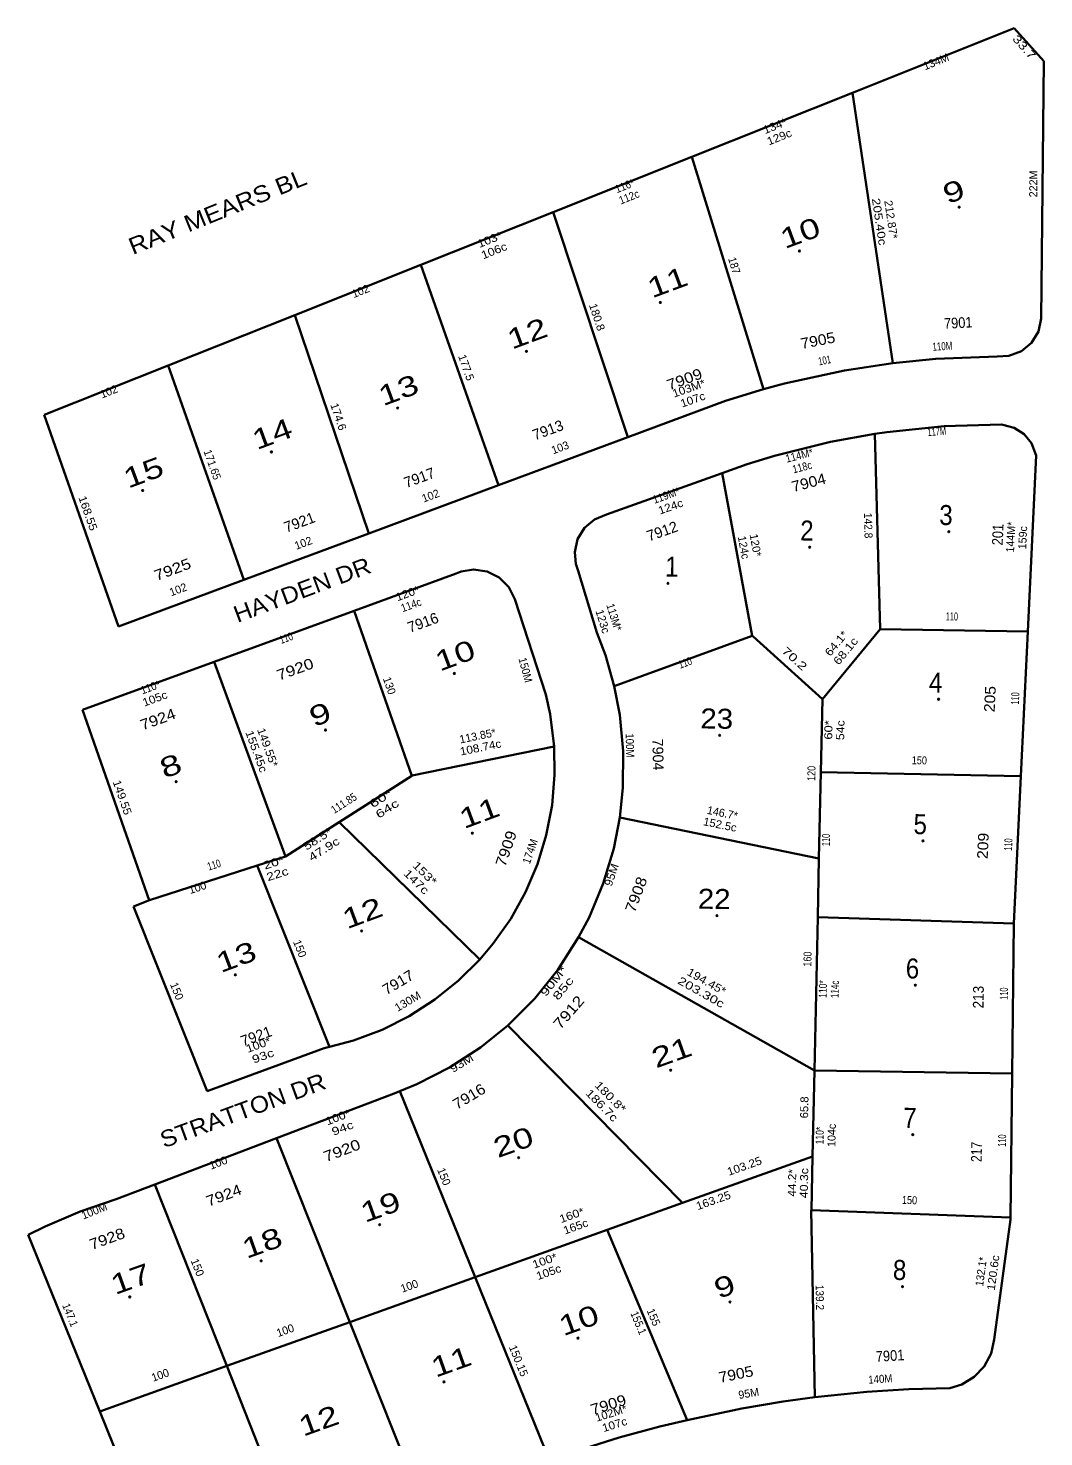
# Model space of a CAD drawing. Extents: x 2546959 to 2550387, y 581906 to 585027.
# Drawn here: x 2547465 to 2548226, y 583970 to 585027 of the extents above; entities that cross this region are included whole.
import ezdxf
from ezdxf.enums import TextEntityAlignment as Align

# ---------------------------------------------------------------- set-up
doc = ezdxf.new("R2010")
doc.units = 0
doc.header["$LTSCALE"] = 2.4
doc.header["$PDMODE"] = 32
doc.header["$PDSIZE"] = 1.2
for name, color, linetype in [('20', 7, 'Continuous'), ('38', 7, 'Continuous'), ('39', 7, 'Continuous'), ('41', 7, 'Continuous'), ('42', 7, 'Continuous')]:
    doc.layers.add(name, color=color, linetype=linetype)
doc.layers.add('40', color=7, linetype='Continuous', lineweight=35)

msp = doc.modelspace()

# ---------------------------------------------------------------- linework, layer by layer
at = {"layer": '40'}
for p, q in [((2548204.014, 585026.501), (2548082.739, 584978.146)), ((2548226.245, 585001.697), (2548204.014, 585026.501)), ((2548224.277, 584808.852), (2548226.245, 585001.697)), ((2548082.739, 584978.146), (2547962.303, 584930.126)), ((2548112.924, 584775.333), (2548082.739, 584978.146)), ((2547962.303, 584930.126), (2547858.204, 584888.62)), ((2548016.151, 584755.782), (2547962.303, 584930.126)), ((2547858.204, 584888.62), (2547759.114, 584849.112)), ((2547914.388, 584719.889), (2547858.204, 584888.62)), ((2547759.114, 584849.112), (2547664.568, 584811.416)), ((2547817.297, 584683.807), (2547759.114, 584849.112)), ((2547664.568, 584811.416), (2547569.517, 584773.517)), ((2547720.206, 584647.727), (2547664.568, 584811.416)), ((2547569.517, 584773.517), (2547476.689, 584736.505)), ((2547626.39, 584612.862), (2547569.517, 584773.517)), ((2547987.542, 584747.075), (2548016.151, 584755.782)), ((2547914.388, 584719.889), (2547987.542, 584747.075)), ((2547476.689, 584736.505), (2547532.448, 584577.95)), ((2547817.297, 584683.807), (2547914.388, 584719.889)), ((2548103.512, 584576.042), (2548099.538, 584722.294)), ((2548003.755, 584699.71), (2547984.922, 584692.969)), ((2548214.27, 584574.238), (2548220.537, 584706.084)), ((2547984.922, 584692.969), (2547898.412, 584662.004)), ((2548007.585, 584570.978), (2547984.922, 584692.969)), ((2547720.206, 584647.727), (2547817.297, 584683.807)), ((2547626.39, 584612.862), (2547720.206, 584647.727)), ((2547532.448, 584577.95), (2547626.39, 584612.862)), ((2547709.072, 584589.763), (2547785.46, 584617.652)), ((2547829.533, 584598.297), (2547852.84, 584526.961)), ((2547752.252, 584465.989), (2547709.072, 584589.763)), ((2548007.585, 584570.978), (2547904.091, 584533.141)), ((2548008.322, 584570.311), (2548007.585, 584570.978)), ((2548060.181, 584523.422), (2548008.322, 584570.311)), ((2548060.181, 584523.422), (2548103.512, 584576.042)), ((2548103.512, 584576.042), (2548214.27, 584574.238)), ((2548209.112, 584465.708), (2548214.27, 584574.238)), ((2547505.384, 584515.396), (2547604.222, 584551.482)), ((2547505.384, 584515.396), (2547555.274, 584372.68)), ((2547697.97, 584431.3), (2547752.252, 584465.989)), ((2548209.112, 584465.708), (2548059.011, 584468.839)), ((2548203.861, 584355.253), (2548209.112, 584465.708)), ((2548057.619, 584403.911), (2547908.224, 584434.685)), ((2547657.54, 584405.464), (2547697.97, 584431.3)), ((2547697.97, 584431.3), (2547803.347, 584328.288)), ((2547636.483, 584398.714), (2547657.54, 584405.464)), ((2547636.483, 584398.714), (2547690.507, 584262.679)), ((2547555.553, 584372.77), (2547543.687, 584368.085)), ((2547543.687, 584368.085), (2547598.762, 584229.478)), ((2548203.861, 584355.253), (2548202.493, 584242.777)), ((2548054.214, 584245.13), (2547877.415, 584344.957)), ((2547955.225, 584145.719), (2547824.237, 584278.814)), ((2547686.611, 584261.811), (2547598.762, 584229.478)), ((2547690.507, 584262.679), (2547686.611, 584261.811)), ((2548052.831, 584180.633), (2548054.214, 584245.13)), ((2548202.493, 584242.777), (2548201.181, 584134.88)), ((2547739.134, 584227.906), (2547650.734, 584194.276)), ((2547743.36, 584229.523), (2547739.134, 584227.906)), ((2547799.804, 584090.124), (2547743.36, 584229.523)), ((2547650.734, 584194.276), (2547559.711, 584159.647)), ((2547705.757, 584056.483), (2547650.734, 584194.276)), ((2547955.225, 584145.719), (2548052.831, 584180.633)), ((2548051.967, 584140.339), (2548052.831, 584180.633)), ((2547559.711, 584159.647), (2547530.552, 584148.553)), ((2547613.638, 584023.531), (2547559.711, 584159.647)), ((2548054.645, 584000.017), (2548051.866, 584140.342)), ((2548051.967, 584140.339), (2548051.866, 584140.342)), ((2548201.181, 584134.88), (2548051.967, 584140.339)), ((2548201.161, 584133.322), (2548189.038, 584043.393)), ((2548201.181, 584134.88), (2548201.161, 584133.322)), ((2547518.285, 583989.423), (2547464.644, 584121.761)), ((2547668.847, 583883.672), (2547613.66, 584023.54))]:
    msp.add_line(p, q, dxfattribs=at)
for points in [[(2548191.184, 584780.398), (2548200.115, 584780.809), (2548209.399, 584784.32), (2548217.032, 584790.665), (2548222.178, 584799.151), (2548224.277, 584808.852)], [(2548112.924, 584775.333), (2548145.178, 584778.626), (2548191.184, 584780.398)], [(2548016.151, 584755.782), (2548031.713, 584760.06), (2548076.691, 584769.891), (2548112.924, 584775.333)], [(2548194.544, 584729.359), (2548151.485, 584728.054), (2548108.625, 584723.707), (2548099.538, 584722.294)], [(2548220.537, 584706.084), (2548217.082, 584715.276), (2548211.48, 584722.12), (2548204.06, 584726.936), (2548195.544, 584729.191), (2548194.544, 584729.359)], [(2548099.538, 584722.294), (2548066.18, 584716.339), (2548024.363, 584705.988), (2548003.755, 584699.71)], [(2547898.412, 584662.004), (2547889.229, 584658.263), (2547881.71, 584651.797), (2547876.634, 584643.278), (2547874.528, 584633.588), (2547875.333, 584624.802), (2547877.097, 584619.566), (2547891.035, 584573.532)], [(2547785.46, 584617.652), (2547789.21, 584619.054), (2547798.645, 584620.715), (2547808.722, 584619.231), (2547817.816, 584614.642), (2547824.998, 584607.418), (2547829.533, 584598.297)], [(2547657.54, 584405.464), (2547604.222, 584551.482), (2547709.072, 584589.763)], [(2547891.035, 584573.532), (2547897.495, 584556.359), (2547904.091, 584533.141)], [(2547852.84, 584526.961), (2547856.068, 584512.098), (2547859.021, 584487.888)], [(2547904.091, 584533.141), (2547908.238, 584511.815), (2547910.874, 584484.426), (2547910.612, 584456.912), (2547908.224, 584434.685)], [(2548203.861, 584355.253), (2548056.679, 584360.068), (2548057.619, 584403.911), (2548059.011, 584468.839), (2548060.181, 584523.422)], [(2547752.252, 584465.989), (2547752.479, 584466.134), (2547859.021, 584487.888)], [(2547859.021, 584487.888), (2547859.399, 584466.668), (2547857.459, 584443.942), (2547853.138, 584421.547), (2547846.481, 584399.732), (2547837.564, 584378.739), (2547826.485, 584358.802), (2547813.367, 584340.144), (2547803.347, 584328.288)], [(2547908.224, 584434.685), (2547903.752, 584411.608), (2547895.859, 584385.249), (2547885.232, 584359.868), (2547877.415, 584344.957)], [(2547555.274, 584372.68), (2547555.553, 584372.77), (2547636.483, 584398.714)], [(2548202.493, 584242.777), (2548054.214, 584245.13), (2548056.679, 584360.068)], [(2547877.415, 584344.957), (2547861.784, 584320.502), (2547844.527, 584299.07), (2547824.237, 584278.814)], [(2547803.347, 584328.288), (2547787.382, 584312.442), (2547769.599, 584298.159), (2547750.411, 584285.83), (2547730.03, 584275.59), (2547708.684, 584267.554), (2547690.507, 584262.679)], [(2547824.237, 584278.814), (2547803.746, 584262.235), (2547780.676, 584247.241), (2547756.154, 584234.761), (2547743.36, 584229.523)], [(2547530.552, 584148.553), (2547503.636, 584139.218), (2547477.436, 584128.032), (2547464.644, 584121.761)], [(2547958.685, 583982.997), (2547898.743, 584125.514), (2547955.225, 584145.719)], [(2547855.466, 583952.653), (2547799.804, 584090.124), (2547898.743, 584125.514)], [(2547761.113, 583917.857), (2547705.757, 584056.483), (2547799.804, 584090.124)], [(2547613.638, 584023.531), (2547613.66, 584023.54), (2547705.757, 584056.483)], [(2548155.677, 584006.992), (2548164.796, 584009.704), (2548174.102, 584015.309), (2548181.577, 584023.194), (2548186.68, 584032.787), (2548189.038, 584043.393)], [(2547575.211, 583848.979), (2547518.285, 583989.423), (2547613.638, 584023.531)], [(2547958.685, 583982.997), (2547999.751, 583991.67), (2548030.843, 583996.867), (2548054.645, 584000.017)], [(2548054.645, 584000.017), (2548093.467, 584004.073), (2548124.926, 584006.073), (2548155.677, 584006.992)], [(2547855.466, 583952.653), (2547877.689, 583960.409), (2547907.788, 583969.778), (2547938.188, 583978.118), (2547958.685, 583982.997)]]:
    msp.add_lwpolyline(points, dxfattribs=at)
at = {"layer": '41'}
for p in [(2548162.752, 584892.32), (2548043.004, 584859.485), (2547938.708, 584820.856), (2547838.274, 584784.159), (2547741.704, 584741.667), (2547647.064, 584708.833), (2547550.494, 584679.862), (2548155.025, 584648.96), (2548050.729, 584637.372), (2547944.501, 584610.332), (2547784.194, 584542.731), (2548147.299, 584523.418), (2547687.623, 584500.24), (2547983.129, 584496.378), (2547575.601, 584461.611), (2547797.714, 584422.983), (2548135.71, 584417.19), (2547981.197, 584361.178), (2547714.663, 584349.588), (2547620.023, 584316.754), (2548129.916, 584309.03), (2547946.432, 584245.293), (2548127.984, 584197.008), (2547832.478, 584179.624), (2547728.182, 584129.406), (2547639.337, 584102.366), (2548120.258, 584083.054), (2547540.835, 584075.326), (2547990.854, 584071.464), (2547876.9, 584044.424), (2547776.467, 584011.59)]:
    msp.add_point(p, dxfattribs=at)

# ---------------------------------------------------------------- texts
at = {"layer": '20'}
for s, rotation, width, p in [('RAY MEARS BL', 22.079, 1.15, (2547608.953, 584883.111)), ('HAYDEN DR', 20.548, 1.1, (2547672.257, 584599.551)), ('STRATTON DR', 20.187, 1.1, (2547627.783, 584209.234))]:
    msp.add_text(s, height=12.5, rotation=rotation, dxfattribs=dict(at, width=width)).set_placement(p, align=Align.CENTER)
at = {"layer": '38'}
for s, rotation, width, p in [('9', 20.386, 1.4, (2548161.296, 584897.085)), ('10', 20.386, 1.35, (2548046.161, 584866.066)), ('11', 20.386, 1.35, (2547946.545, 584829.075)), ('12', 20.386, 1.35, (2547841.47, 584790.653)), ('13', 20.386, 1.35, (2547744.885, 584748.2)), ('14', 20.386, 1.35, (2547650.22, 584715.347)), ('15', 20.386, 1.35, (2547553.688, 584686.44)), ('3', 359.091, 0.9, (2548152.769, 584653.988)), ('2', 359.091, 0.9, (2548048.45, 584642.361)), ('1', 359.091, 0.9, (2547947.172, 584615.296)), ('10', 20.386, 1.35, (2547787.39, 584549.269)), ('4', 359.091, 0.9, (2548145.035, 584528.443)), ('9', 20.386, 1.4, (2547686.155, 584505.088)), ('23', 359.091, 1.1, (2547980.878, 584501.35)), ('8', 20.386, 1.4, (2547574.103, 584466.474)), ('11', 20.386, 1.35, (2547805.532, 584431.211)), ('5', 359.091, 0.9, (2548133.462, 584422.204)), ('22', 359.091, 1.1, (2547978.957, 584366.204)), ('12', 20.386, 1.35, (2547717.844, 584356.097)), ('13', 20.386, 1.35, (2547623.179, 584323.244)), ('6', 359.091, 0.9, (2548127.648, 584314.045)), ('21', 19.682, 1.35, (2547949.625, 584251.651)), ('7', 359.091, 0.9, (2548125.728, 584202.046)), ('20', 19.682, 1.35, (2547830.982, 584184.38)), ('19', 19.682, 1.35, (2547731.334, 584135.811)), ('18', 19.682, 1.35, (2547642.536, 584108.825)), ('17', 19.682, 1.35, (2547544.031, 584081.731)), ('8', 359.091, 0.9, (2548117.994, 584088.02)), ('9', 19.682, 1.35, (2547989.379, 584076.222)), ('10', 19.682, 1.35, (2547880.079, 584050.799)), ('11', 19.682, 1.35, (2547784.324, 584019.723)), ('12', 19.682, 1.35, (2547684.988, 583975.493))]:
    msp.add_text(s, height=15, rotation=rotation, dxfattribs=dict(at, width=width)).set_placement(p, align=Align.CENTER)
at = {"layer": '39'}
for s, rotation, width, p in [('7901', 3.218, 0.9, (2548162.286, 584801.623)), ('7905', 11.318, 1.1, (2548057.568, 584788.457)), ('7909', 20.386, 1.15, (2547958.146, 584759.551)), ('7904', 14.917, 1.1, (2548050.963, 584681.966)), ('201', 87.279, 0.9, (2548195.683, 584646.653)), ('7925', 20.387, 1.2, (2547574.257, 584616.937)), ('7920', 20.057, 1.2, (2547666.159, 584542.14)), ('205', 87.279, 1.1, (2548189.811, 584523.318)), ('7924', 20.057, 1.15, (2547563.281, 584504.594)), ('7909', 71.017, 1.15, (2547826.789, 584410.146)), ('209', 87.279, 1.1, (2548184.585, 584413.24)), ('7908', 69.293, 1.15, (2547924.274, 584375.587)), ('7917', 30.71, 1.05, (2547744.054, 584307.711)), ('213', 89.303, 0.95, (2548181.137, 584300.02)), ('7912', 49.143, 1.2, (2547873.001, 584286.096)), ('7916', 31.003, 1.1, (2547797.322, 584222.189)), ('7920', 20.829, 1.2, (2547701.299, 584181.35)), ('217', 89.303, 0.85, (2548179.751, 584183.968)), ('7924', 20.829, 1.15, (2547612.767, 584147.75)), ('7928', 20.125, 1.15, (2547525.209, 584115.163)), ('7901', 3.638, 0.9, (2548111.197, 584027.229)), ('7905', 11.44, 1.1, (2547996.197, 584013.43)), ('7909', 17.29, 1.15, (2547900.881, 583990.701))]:
    msp.add_text(s, height=8, rotation=rotation, dxfattribs=dict(at, width=width)).set_placement(p, align=Align.CENTER)
for s, rotation, p in [('7913', 20.386, (2547855.743, 584721.49)), ('7917', 20.386, (2547759.371, 584685.756)), ('7921', 20.386, (2547669.442, 584652.309)), ('7912', 19.694, (2547941.455, 584645.626)), ('7916', 20.057, (2547762.043, 584577.16)), ('7904', 271.467, (2547932.962, 584481.833)), ('7921', 20.206, (2547636.99, 584267.022))]:
    msp.add_text(s, height=8, rotation=rotation, dxfattribs=at).set_placement(p, align=Align.CENTER)
at = {"layer": '42'}
for s, rotation, width, p in [('33.7', 311.868, 1.35, (2548209.268, 585010.333)), ('134*', 21.738, 1.1, (2548025.661, 584950.415)), ('129c', 21.738, 1.1, (2548028.967, 584942.094)), ('116*', 21.738, 0.9, (2547913.044, 584905.475)), ('112c', 21.738, 0.9, (2547916.351, 584897.154)), ('205.40c', 278.465, 1.25, (2548099.927, 584880.975)), ('212.87*', 278.465, 1.05, (2548108.724, 584882.629)), ('103*', 21.738, 1.15, (2547811.796, 584865.189)), ('106c', 21.738, 1.15, (2547815.103, 584856.868)), ('187', 287.164, 0.95, (2547991.272, 584847.702)), ('180.8', 288.417, 1.05, (2547888.394, 584808.962)), ('110M', 3.703, 0.75, (2548150.353, 584785.07)), ('101', 11.318, 0.65, (2548062.418, 584774.558)), ('103M*', 19.429, 1.1, (2547961.003, 584753.71)), ('107c', 19.429, 1.1, (2547963.989, 584745.178)), ('174.6', 288.773, 1.05, (2547694.493, 584734.26)), ('117M', 4.253, 0.7, (2548146.198, 584721.176)), ('171.65', 289.494, 0.95, (2547599.95, 584698.275)), ('114M*', 14.352, 0.9, (2548043.53, 584703.277)), ('118c', 14.352, 0.85, (2548045.77, 584694.53)), ('168.55', 289.375, 1.1, (2547506.685, 584661.879)), ('119M*', 19.694, 0.9, (2547944.033, 584673.383)), ('124c', 19.694, 1.1, (2547947.376, 584664.978)), ('142.8', 271.556, 0.95, (2548091.607, 584653.488)), ('120*', 280.524, 1.05, (2548007.165, 584638.363)), ('120*', 20.057, 1.1, (2547750.081, 584599.929)), ('114c', 20.057, 0.9, (2547752.819, 584591.266)), ('123c', 287.345, 1.05, (2547892.667, 584580.912)), ('113M*', 287.345, 0.9, (2547901.195, 584584.047)), ('110', 359.067, 0.6, (2548157.27, 584582.447)), ('110', 20.057, 0.75, (2547659.115, 584566.519)), ('64.1*', 50.53, 1.15, (2548072.98, 584563.384)), ('70.2', 317.881, 1.4, (2548037.282, 584551.631)), ('68.1c', 50.53, 1.2, (2548079.913, 584557.623)), ('150M', 284.954, 0.95, (2547834.709, 584544.572)), ('110', 20.082, 0.75, (2547958.313, 584547.962)), ('110*', 20.057, 0.9, (2547557.25, 584529.507)), ('105c', 20.057, 1.1, (2547560.698, 584521.102)), ('110', 87.279, 0.6, (2548207.712, 584523.88)), ('60*', 88.772, 1.2, (2548067.694, 584500.316)), ('54c', 88.772, 1.15, (2548076.654, 584500.103)), ('155.45c', 290.059, 1.15, (2547633.01, 584483.252)), ('149.55*', 290.059, 1.1, (2547641.435, 584486.239)), ('100M', 271.467, 0.9, (2547912.89, 584488.698)), ('108.74c', 11.54, 1.1, (2547804.461, 584484.303)), ('150', 358.805, 0.85, (2548132.848, 584474.604)), ('120', 88.772, 0.85, (2548054.939, 584467.724)), ('149.55', 289.268, 1.1, (2547532.439, 584448.771)), ('111.85', 32.581, 0.85, (2547702.975, 584442.956)), ('60*', 32.581, 1.5, (2547730.65, 584446.447)), ('64c', 32.581, 1.45, (2547735.45, 584438.767)), ('152.5c', 348.36, 1.05, (2547982.832, 584426.503)), ('58.5*', 32.58, 1.25, (2547683.29, 584416.154)), ('110', 88.771, 0.6, (2548065.864, 584417.854)), ('47.9c', 32.58, 1.3, (2547688.091, 584408.475)), ('174M', 71.017, 0.95, (2547843.853, 584408.332)), ('110', 87.279, 0.6, (2548202.538, 584414.335)), ('110', 17.774, 0.75, (2547604.905, 584396.401)), ('20*', 17.774, 1.3, (2547649.678, 584398.019)), ('153*', 315.65, 1.3, (2547759.949, 584390.785)), ('95M', 71.313, 1.1, (2547904.876, 584390.77)), ('22c', 17.774, 1.3, (2547652.451, 584389.486)), ('147c', 315.65, 1.3, (2547753.656, 584384.385)), ('160', 88.772, 0.85, (2548052.006, 584328.526)), ('90M*', 51.157, 1.4, (2547861.028, 584310.237)), ('194.45*', 330.549, 1.15, (2547971.886, 584309.218)), ('85c', 51.157, 1.5, (2547868.068, 584304.69)), ('203.30c', 330.549, 1.35, (2547967.842, 584301.139)), ('110*', 88.772, 0.8, (2548063.517, 584306.069)), ('114c', 88.772, 0.75, (2548072.478, 584305.855)), ('110', 89.303, 0.6, (2548199.255, 584302.655)), ('130M', 30.71, 1.05, (2547750.744, 584294.295)), ('100*', 20.206, 1.15, (2547638.257, 584261.486)), ('93c', 20.206, 1.3, (2547641.705, 584253.083)), ('93M', 31.003, 1.2, (2547791.255, 584248.008)), ('180.8*', 314.543, 1.25, (2547899.083, 584223.205)), ('186.7c', 314.543, 1.25, (2547892.684, 584216.805)), ('65.8', 88.772, 1.05, (2548049.614, 584217.332)), ('100*', 20.829, 1.15, (2547697.893, 584207.225)), ('94c', 20.829, 1.3, (2547701.446, 584199.04)), ('110*', 88.772, 0.8, (2548061.171, 584196.203)), ('110', 89.303, 0.6, (2548197.921, 584192.471)), ('100', 20.829, 1.05, (2547608.186, 584173.092)), ('103.25', 19.682, 1.1, (2548002.732, 584170.582)), ('44.2*', 88.771, 1.1, (2548040.436, 584160.762)), ('40.3c', 88.771, 1.15, (2548049.396, 584160.548)), ('163.25', 19.682, 1.1, (2547979.475, 584144.838)), ('150', 357.905, 0.85, (2548125.434, 584144.905)), ('160*', 19.682, 1.15, (2547873.187, 584133.782)), ('165c', 19.682, 1.1, (2547876.174, 584125.248)), ('100*', 19.682, 1.15, (2547852.97, 584099.611)), ('132.1*', 82.322, 0.95, (2548182.176, 584093.917)), ('120.6c', 82.322, 1.1, (2548191.187, 584093.012)), ('105c', 19.682, 1.1, (2547855.956, 584091.078)), ('139.2', 271.134, 0.95, (2548055.287, 584074.871)), ('147.1', 292.064, 0.9, (2547493.436, 584060.622)), ('155.1', 292.811, 0.9, (2547919.601, 584054.68)), ('140M', 3.949, 0.9, (2548103.821, 584010.81)), ('102M*', 17.29, 1.05, (2547902.597, 583985.301)), ('107c', 17.29, 1.1, (2547905.264, 583976.768))]:
    msp.add_text(s, height=5.999, rotation=rotation, dxfattribs=dict(at, width=width)).set_placement(p, align=Align.CENTER)
for s, rotation, p in [('134M', 21.738, (2548146.512, 584998.628)), ('222M', 89.416, (2548221.346, 584909.698)), ('102', 21.738, (2547714.998, 584826.575)), ('177.5', 289.391, (2547790.309, 584771.102)), ('102', 21.738, (2547526.254, 584751.268)), ('103', 20.386, (2547864.567, 584709.277)), ('102', 20.386, (2547767.448, 584673.117)), ('144M*', 87.279, (2548204.425, 584644.792)), ('102', 20.386, (2547671.983, 584637.704)), ('124c', 280.524, (2547998.312, 584636.657)), ('159c', 87.279, (2548213.384, 584644.365)), ('102', 20.387, (2547578.117, 584602.825)), ('130', 289.232, (2547732.754, 584532.614)), ('113.85*', 11.54, (2547802.279, 584492.973)), ('146.7*', 348.36, (2547984.645, 584435.249)), ('100', 18.266, (2547592.516, 584379.366)), ('150', 291.66, (2547665.625, 584335.359)), ('150', 291.67, (2547573.36, 584303.465)), ('104c', 88.772, (2548070.138, 584196.367)), ('150', 292.043, (2547773.698, 584164.442)), ('100M', 21.728, (2547515.318, 584136.98)), ('150', 291.613, (2547588.824, 584096.326)), ('100', 19.682, (2547751.482, 584080.661)), ('155', 292.811, (2547930.859, 584058.981)), ('100', 19.682, (2547658.417, 584047.381)), ('150.15', 292.043, (2547829.608, 584026.341)), ('100', 19.682, (2547564.658, 584013.888)), ('95M', 9.489, (2548005.416, 584000.057))]:
    msp.add_text(s, height=5.999, rotation=rotation, dxfattribs=at).set_placement(p, align=Align.CENTER)

doc.saveas('drawing.dxf')
